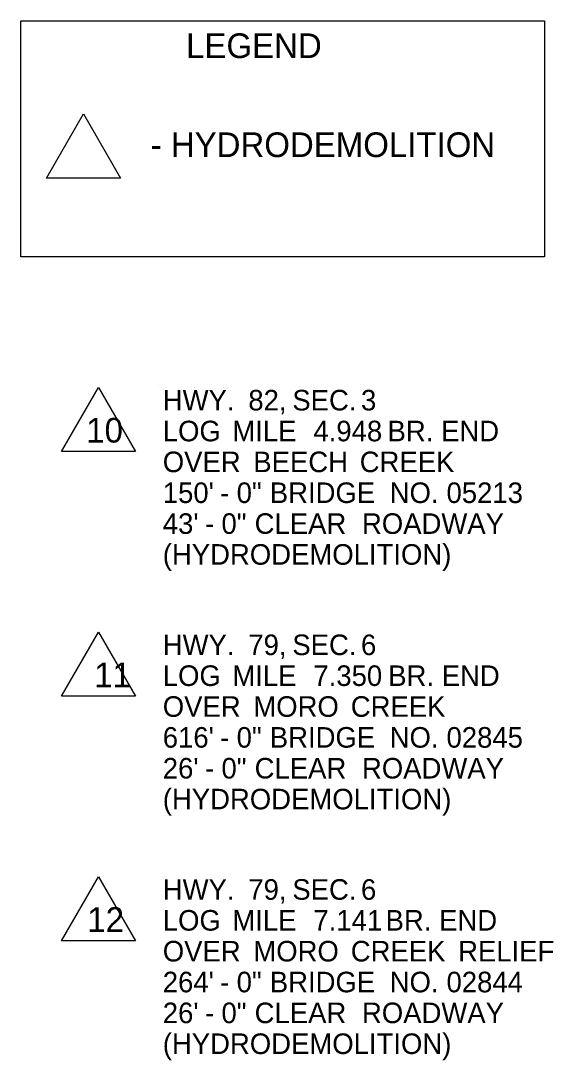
# Model space of a CAD drawing. Extents: x -17742 to 32032, y -17264 to 5867.
# Drawn here: x -17066 to -15123, y -15308 to -11517 of the extents above; entities that cross this region are included whole.
import ezdxf

# ---------------------------------------------------------------- set-up
doc = ezdxf.new("R2010")
doc.units = 0
doc.layers.add('Default', color=7, linetype='Continuous')
doc.layers.add('R_Annotation', color=7, linetype='Continuous')

msp = doc.modelspace()

# ---------------------------------------------------------------- linework, layer by layer
at = {"layer": 'R_Annotation'}
msp.add_line((-16562.1, -12848.3), (-16562.1, -12848.3), dxfattribs=at)
for points in [[(-17065.7, -11517.4), (-15155.1, -11517.4), (-15155.1, -12378.6), (-17065.7, -12378.6)], [(-16836.4, -11857.2), (-16701.4, -12091), (-16971.4, -12091)], [(-16782.5, -12854.5), (-16647.5, -13088.3), (-16917.5, -13088.3)], [(-16782.5, -13746.6), (-16647.5, -13980.4), (-16917.5, -13980.4)], [(-16782.5, -14638.7), (-16647.5, -14872.5), (-16917.5, -14872.5)]]:
    msp.add_lwpolyline(points, close=True, dxfattribs=at)

# ---------------------------------------------------------------- texts
at = {"layer": 'Default'}
for s, p in [('HWY.', (-16547.5, -12938.3)), (' 82,', (-16263.2, -12938.3)), (' SEC.', (-16102.6, -12938.3)), (' 3', (-15852.1, -12938.3)), ('LOG', (-16547.5, -13050.8)), (' MILE', (-16321.5, -13050.8)), (' 4.948', (-16025.7, -13050.8)), (' BR.', (-15755.1, -13050.8)), (' END', (-15559.9, -13050.8)), ('OVER', (-16547.5, -13163.3)), (' BEECH', (-16245, -13163.3)), (' CREEK', (-15856.7, -13163.3)), ("150'", (-16547.5, -13275.8)), (' 0"', (-16305.8, -13275.8)), (' BRIDGE', (-16184.8, -13275.8)), (' NO.', (-15747.4, -13275.8)), (' 05213', (-15540, -13275.8)), (' -', (-16366, -13275.8)), ("43'", (-16547.5, -13388.3)), (' 0"', (-16361.2, -13388.3)), (' CLEAR', (-16240.2, -13388.3)), (' ROADWAY', (-15848.5, -13388.3)), (' -', (-16421.4, -13388.3)), ('(HYDRODEMOLITION)', (-16547.5, -13500.8)), ('HWY.', (-16547.5, -13830.4)), (' 79,', (-16263.2, -13830.4)), (' SEC.', (-16102.6, -13830.4)), (' 6', (-15852.1, -13830.4)), ('LOG', (-16547.5, -13942.9)), (' MILE', (-16321.5, -13942.9)), (' 7.350', (-16025.7, -13942.9)), (' BR.', (-15752.7, -13942.9)), (' END', (-15557.5, -13942.9)), ('OVER', (-16547.5, -14055.4)), (' MORO', (-16245, -14055.4)), (' CREEK', (-15889.3, -14055.4)), ("616'", (-16547.5, -14167.9)), (' 0"', (-16305.8, -14167.9)), (' BRIDGE', (-16184.8, -14167.9)), (' NO.', (-15747.4, -14167.9)), (' 02845', (-15540, -14167.9)), (' -', (-16366, -14167.9)), ("26'", (-16547.5, -14280.4)), (' 0"', (-16361.2, -14280.4)), (' CLEAR', (-16240.2, -14280.4)), (' ROADWAY', (-15848.5, -14280.4)), (' -', (-16421.4, -14280.4)), ('(HYDRODEMOLITION)', (-16547.5, -14392.9)), ('HWY.', (-16547.5, -14722.5)), (' 79,', (-16263.2, -14722.5)), (' SEC.', (-16102.6, -14722.5)), (' 6', (-15852.1, -14722.5)), ('LOG', (-16547.5, -14835)), (' MILE', (-16321.5, -14835)), (' 7.141', (-16025.7, -14835)), (' BR.', (-15762.3, -14835)), (' END', (-15567.1, -14835)), ('OVER', (-16547.5, -14947.5)), (' MORO', (-16245, -14947.5)), (' CREEK', (-15889.3, -14947.5)), (' RELIEF', (-15497.7, -14947.5)), ("264'", (-16547.5, -15060)), (' 0"', (-16305.8, -15060)), (' BRIDGE', (-16184.8, -15060)), (' NO.', (-15747.4, -15060)), (' 02844', (-15540, -15060)), (' -', (-16366, -15060)), ("26'", (-16547.5, -15172.5)), (' 0"', (-16361.2, -15172.5)), (' CLEAR', (-16240.2, -15172.5)), (' ROADWAY', (-15848.5, -15172.5)), (' -', (-16421.4, -15172.5)), ('(HYDRODEMOLITION)', (-16547.5, -15285))]:
    msp.add_text(s, height=75, dxfattribs=at).set_placement(p)
at = {"layer": 'R_Annotation'}
for s, p in [('LEGEND', (-16462.4, -11653.2)), ('- HYDRODEMOLITION', (-16591.6, -12014.3)), ('10', (-16826.8, -13055.3)), ('11', (-16797.4, -13947.5)), ('12', (-16822.9, -14839.6))]:
    msp.add_text(s, height=90, dxfattribs=at).set_placement(p)

doc.saveas('drawing.dxf')
